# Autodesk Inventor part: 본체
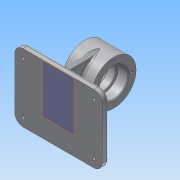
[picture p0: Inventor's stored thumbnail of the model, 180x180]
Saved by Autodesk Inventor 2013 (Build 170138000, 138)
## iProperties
Created: 2019-09
Part Number: 본체
Material: 알루미늄 6061
Document SubType Name: Modeling
Designer: Administrator
Density: 2.71 g/cm^3
Mass: 556.359 g
Surface Area: 494.585 cm^2
Volume: 205.299 cm^3
Author: Administrator
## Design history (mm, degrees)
sketch "스케치1"
  geometry: C1 r 32 at (0, 0); 1 further point
  constraints: 1 centre point, 1 coincident
  dimensions: "d0" = 64 diameter of C1
extrude "돌출1" new body sketch "스케치1" stored distance "d1" = 42; taper "d2" = 0 deg
node "작업 평면3"
sketch "스케치2"
  geometry: L1 (63, -62)-(-63, -62); L2 (-63, -62)-(-63, 36); L3 (-63, 36)-(63, 36); L4 (63, 36)-(63, -62); 2 further points
  constraints: 8 end point, 2 parallel, 1 horizontal, 1 midpoint, 1 perpendicular, 1 vertical alignment
  dimensions: "d5" = 126 distance of L2.end L3.end; "d6" = 98 distance of L1.end L2.end; "d7" = 36 distance from line of point (0, 0) L3
extrude "돌출2" join sketch "스케치2" distance "d8" = 9; taper "d9" = 0 deg
sketch "스케치4"
  geometry: L1 (-4, 32)-(4, 32); L2 (4, 32)-(4, -32); L3 (4, -32)-(-4, -32); L4 (-4, -32)-(-4, 32); L5 (-4, 32)-(4, -32); L6 (4, 32)-(-4, -32); L7 (-17, 4)-(17, 4); L8 (17, 4)-(17, -4); L9 (17, -4)-(-17, -4); L10 (-17, -4)-(-17, 4); L11 (-17, 4)-(17, -4); L12 (17, 4)-(-17, -4); 1 further point
  constraints: 24 end point, 4 midpoint, 4 parallel, 2 horizontal, 2 perpendicular
  dimensions: "d24" = 8 distance of L2.end L3.end; "d25" = 64 distance of L1.end L2.end; "d26" = 34 distance of L8.end L9.end; "d27" = 8 distance of L7.end L8.end
extrude "돌출3" join sketch "스케치4" stored distance "d28" = 9; taper "d29" = 0 deg
hole "구멍1" diameter "d32" = 36; stored, may be unused: countersink angle "d36" = 90 deg, drill point angle "d38" = 0 deg; dims "d30" = 10, "d31" = 10, "d33" = 6, "d34" = 42, "d35" = 15, "d37" = 21
hole "구멍2" diameter "d41" = 36; stored, may be unused: countersink angle "d45" = 90 deg, drill point angle "d47" = 0 deg; dims "d39" = 10, "d40" = 10, "d42" = 6, "d43" = 42, "d44" = 15, "d46" = 21
sketch "스케치5" dims "d48" = 52
  geometry: C1 r 32 at (0, 0) reference; 2 further points
  constraints: 2 vertical alignment, 1 coincident, 2 other
hole "구멍3" sketch "스케치5" at (0, 26) diameter "d49" = 3.242; stored, may be unused: countersink angle "d53" = 90 deg, drill point angle "d55" = 118 deg; dims "d50" = 8, "d51" = 42, "d52" = 15, "d54" = 10
fillet "모깎기1" dims "d59" = 12
sketch "스케치6"
  geometry: A1 r 12 centre (-51, -24) between (-63, -24) and (-51, -36) reference; A2 r 12 centre (51, -24) between (51, -36) and (63, -24) reference; A3 r 12 centre (51, 50) between (63, 50) and (51, 62) reference; A4 r 12 centre (-51, 50) between (-51, 62) and (-63, 50) reference; 1 further point
hole "구멍4" sketch "스케치6" at (-51, 50), (-51, -24), (51, -24), (51, 50) diameter "d60" = 4.5; stored, may be unused: countersink angle "d64" = 90 deg, drill point angle "d66" = 118 deg; dims "d61" = 8, "d62" = 8, "d63" = 4.4, "d65" = 10
sketch "스케치7"
  geometry: L1 (63, -24)-(63, 50) reference; L2 (51, 62)-(-51, 62) reference; 2 further points
  constraints: 1 other
  dimensions: "d67" = 10 distance from line of L2 point (0, 52); "d68" = 63 distance from line of L1 point (0, 52)
feature "엠보싱1" sketch "스케치7" dims "d26" = 34, "d27" = 8, "d69" = 0.5, "d70" = 0
fillet "모깎기2" dims "d71" = 3
chamfer "모따기1" distance "d77" = 1; stored, may be unused: second distance "d78" = 2, angle "d79" = 45 deg
fillet "모깎기8" dims "d80" = 0.3
fillet "모깎기11" dims "d83" = 3
fillet "모깎기12" dims "d84" = 3
fillet "모깎기13" dims "d85" = 3
fillet "모깎기14" dims "d86" = 3
node "솔리드1"
pattern_circular "원형 패턴1" dims angle "d57" = 360 deg
mirror "대칭1"
other parameters: "d4" = -59
